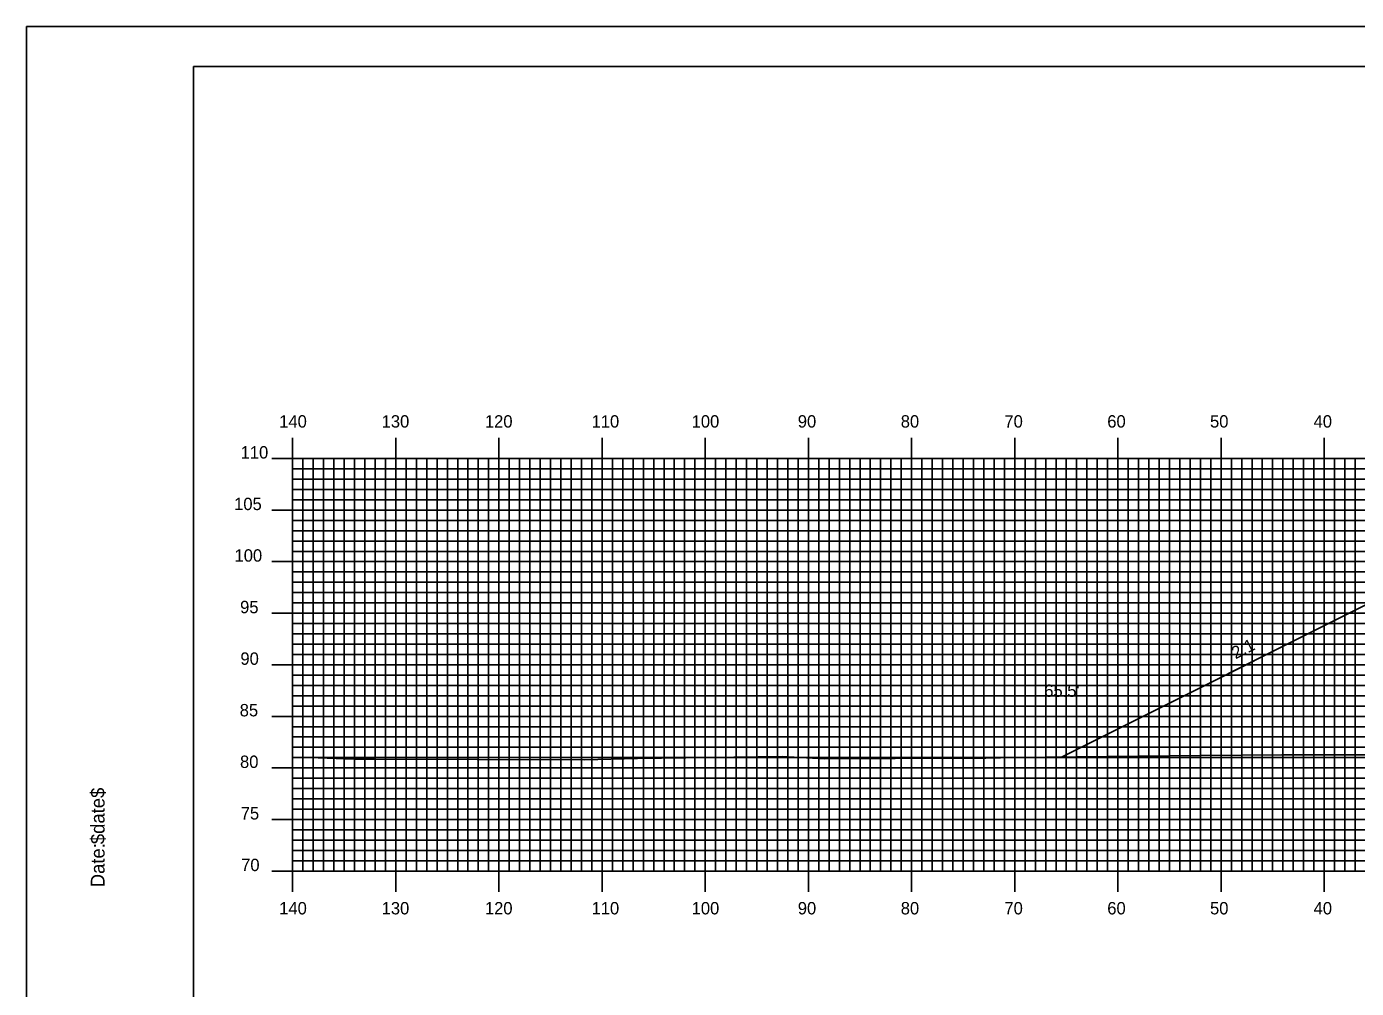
# Model space of a CAD drawing. Extents: x 1758643 to 1758986, y 442591 to 442811.
# Drawn here: x 1758642.9 to 1758771.8, y 442717.3 to 442810.5 of the extents above; entities that cross this region are included whole.
import ezdxf

# ---------------------------------------------------------------- set-up
doc = ezdxf.new("R2010")
doc.units = 0
for name, color, linetype in [('ANNOTATION', 7, 'Continuous'), ('BORDER', 7, 'Continuous'), ('D_Roadway_Centerline', 7, 'Continuous'), ('D_Roadway_SlopeLines', 7, 'Continuous'), ('D_Text_Standard', 7, 'Continuous'), ('H_V ANNOTATION', 7, 'Continuous'), ('MAJOR', 7, 'Continuous'), ('MINOR', 7, 'Continuous'), ('PLOT BOUNDARY', 7, 'Continuous'), ('S_Roadway_Centerline', 7, 'Continuous')]:
    doc.layers.add(name, color=color, linetype=linetype)

msp = doc.modelspace()

# ---------------------------------------------------------------- linework, layer by layer
at = {"layer": 'BORDER'}
msp.add_lwpolyline([(1758659.05, 442596.67), (1758979.05, 442596.67), (1758979.05, 442806.67), (1758659.05, 442806.67)], close=True, dxfattribs=at)
at = {"layer": 'D_Roadway_Centerline'}
msp.add_lwpolyline([(1758743.18, 442739.72), (1758775.52, 442755.9), (1758780.64, 442758.45), (1758783.64, 442758.57), (1758791.64, 442758.89), (1758796.65, 442759.05), (1758808.65, 442759.42), (1758820.65, 442759.78), (1758832.65, 442759.68), (1758840.65, 442759.36), (1758843.65, 442759.24), (1758848.4, 442756.87), (1758881.86, 442740.14)], dxfattribs=at)
at = {"layer": 'D_Roadway_SlopeLines'}
msp.add_lwpolyline([(1758780.64, 442758.45), (1758743.18, 442739.72)], dxfattribs=at)
at = {"layer": 'MAJOR'}
for p, q in [((1758668.65, 442770.67), (1758668.65, 442768.67)), ((1758678.65, 442770.67), (1758678.65, 442768.67)), ((1758688.65, 442770.67), (1758688.65, 442768.67)), ((1758698.65, 442770.67), (1758698.65, 442768.67)), ((1758708.65, 442770.67), (1758708.65, 442768.67)), ((1758718.65, 442770.67), (1758718.65, 442768.67)), ((1758728.65, 442770.67), (1758728.65, 442768.67)), ((1758738.65, 442770.67), (1758738.65, 442768.67)), ((1758748.65, 442770.67), (1758748.65, 442768.67)), ((1758758.65, 442770.67), (1758758.65, 442768.67)), ((1758768.65, 442770.67), (1758768.65, 442768.67)), ((1758666.64, 442768.67), (1758668.65, 442768.67)), ((1758668.65, 442768.67), (1758948.65, 442768.67)), ((1758668.65, 442728.67), (1758668.65, 442768.67)), ((1758668.65, 442728.67), (1758668.65, 442768.67)), ((1758668.65, 442768.67), (1758948.65, 442768.67)), ((1758678.65, 442728.67), (1758678.65, 442768.67)), ((1758688.65, 442728.67), (1758688.65, 442768.67)), ((1758698.65, 442728.67), (1758698.65, 442768.67)), ((1758708.65, 442728.67), (1758708.65, 442768.67)), ((1758718.65, 442728.67), (1758718.65, 442768.67)), ((1758728.65, 442728.67), (1758728.65, 442768.67)), ((1758738.65, 442728.67), (1758738.65, 442768.67)), ((1758748.65, 442728.67), (1758748.65, 442768.67)), ((1758758.65, 442728.67), (1758758.65, 442768.67)), ((1758768.65, 442728.67), (1758768.65, 442768.67)), ((1758666.64, 442763.67), (1758668.65, 442763.67)), ((1758668.65, 442763.67), (1758948.65, 442763.67)), ((1758666.64, 442758.67), (1758668.65, 442758.67)), ((1758668.65, 442758.67), (1758948.65, 442758.67)), ((1758666.64, 442753.67), (1758668.65, 442753.67)), ((1758668.65, 442753.67), (1758948.65, 442753.67)), ((1758666.64, 442748.67), (1758668.65, 442748.67)), ((1758668.65, 442748.67), (1758948.65, 442748.67)), ((1758666.64, 442743.67), (1758668.65, 442743.67)), ((1758668.65, 442743.67), (1758948.65, 442743.67)), ((1758666.64, 442738.67), (1758668.65, 442738.67)), ((1758668.65, 442738.67), (1758948.65, 442738.67)), ((1758666.64, 442733.67), (1758668.65, 442733.67)), ((1758668.65, 442733.67), (1758948.65, 442733.67)), ((1758666.64, 442728.67), (1758668.65, 442728.67)), ((1758668.65, 442728.67), (1758948.65, 442728.67)), ((1758668.65, 442728.67), (1758948.65, 442728.67)), ((1758668.65, 442726.66), (1758668.65, 442728.67)), ((1758678.65, 442726.66), (1758678.65, 442728.67)), ((1758688.65, 442726.66), (1758688.65, 442728.67)), ((1758698.65, 442726.66), (1758698.65, 442728.67)), ((1758708.65, 442726.66), (1758708.65, 442728.67)), ((1758718.65, 442726.66), (1758718.65, 442728.67)), ((1758728.65, 442726.66), (1758728.65, 442728.67)), ((1758738.65, 442726.66), (1758738.65, 442728.67)), ((1758748.65, 442726.66), (1758748.65, 442728.67)), ((1758758.65, 442726.66), (1758758.65, 442728.67)), ((1758768.65, 442726.66), (1758768.65, 442728.67))]:
    msp.add_line(p, q, dxfattribs=at)
at = {"layer": 'MINOR'}
for p, q in [((1758668.65, 442767.67), (1758948.65, 442767.67)), ((1758668.65, 442767.67), (1758670.65, 442767.67)), ((1758669.65, 442728.67), (1758669.65, 442768.67)), ((1758670.65, 442728.67), (1758670.65, 442768.67)), ((1758671.65, 442728.67), (1758671.65, 442768.67)), ((1758672.65, 442728.67), (1758672.65, 442768.67)), ((1758673.65, 442728.67), (1758673.65, 442768.67)), ((1758674.65, 442728.67), (1758674.65, 442768.67)), ((1758675.65, 442728.67), (1758675.65, 442768.67)), ((1758676.65, 442728.67), (1758676.65, 442768.67)), ((1758677.65, 442728.67), (1758677.65, 442768.67)), ((1758679.65, 442728.67), (1758679.65, 442768.67)), ((1758680.65, 442728.67), (1758680.65, 442768.67)), ((1758681.65, 442728.67), (1758681.65, 442768.67)), ((1758682.65, 442728.67), (1758682.65, 442768.67)), ((1758683.65, 442728.67), (1758683.65, 442768.67)), ((1758684.65, 442728.67), (1758684.65, 442768.67)), ((1758685.65, 442728.67), (1758685.65, 442768.67)), ((1758686.65, 442728.67), (1758686.65, 442768.67)), ((1758687.65, 442728.67), (1758687.65, 442768.67)), ((1758689.65, 442728.67), (1758689.65, 442768.67)), ((1758690.65, 442728.67), (1758690.65, 442768.67)), ((1758691.65, 442728.67), (1758691.65, 442768.67)), ((1758692.65, 442728.67), (1758692.65, 442768.67)), ((1758693.65, 442728.67), (1758693.65, 442768.67)), ((1758694.65, 442728.67), (1758694.65, 442768.67)), ((1758695.65, 442728.67), (1758695.65, 442768.67)), ((1758696.65, 442728.67), (1758696.65, 442768.67)), ((1758697.65, 442728.67), (1758697.65, 442768.67)), ((1758699.65, 442728.67), (1758699.65, 442768.67)), ((1758700.65, 442728.67), (1758700.65, 442768.67)), ((1758701.65, 442728.67), (1758701.65, 442768.67)), ((1758702.65, 442728.67), (1758702.65, 442768.67)), ((1758703.65, 442728.67), (1758703.65, 442768.67)), ((1758704.65, 442728.67), (1758704.65, 442768.67)), ((1758705.65, 442728.67), (1758705.65, 442768.67)), ((1758706.65, 442728.67), (1758706.65, 442768.67)), ((1758707.65, 442728.67), (1758707.65, 442768.67)), ((1758709.65, 442728.67), (1758709.65, 442768.67)), ((1758710.65, 442728.67), (1758710.65, 442768.67)), ((1758711.65, 442728.67), (1758711.65, 442768.67)), ((1758712.65, 442728.67), (1758712.65, 442768.67)), ((1758713.65, 442728.67), (1758713.65, 442768.67)), ((1758714.65, 442728.67), (1758714.65, 442768.67)), ((1758715.65, 442728.67), (1758715.65, 442768.67)), ((1758716.65, 442728.67), (1758716.65, 442768.67)), ((1758717.65, 442728.67), (1758717.65, 442768.67)), ((1758719.65, 442728.67), (1758719.65, 442768.67)), ((1758720.65, 442728.67), (1758720.65, 442768.67)), ((1758721.65, 442728.67), (1758721.65, 442768.67)), ((1758722.65, 442728.67), (1758722.65, 442768.67)), ((1758723.65, 442728.67), (1758723.65, 442768.67)), ((1758724.65, 442728.67), (1758724.65, 442768.67)), ((1758725.65, 442728.67), (1758725.65, 442768.67)), ((1758726.65, 442728.67), (1758726.65, 442768.67)), ((1758727.65, 442728.67), (1758727.65, 442768.67)), ((1758729.65, 442728.67), (1758729.65, 442768.67)), ((1758730.65, 442728.67), (1758730.65, 442768.67)), ((1758731.65, 442728.67), (1758731.65, 442768.67)), ((1758732.65, 442728.67), (1758732.65, 442768.67)), ((1758733.65, 442728.67), (1758733.65, 442768.67)), ((1758734.65, 442728.67), (1758734.65, 442768.67)), ((1758735.65, 442728.67), (1758735.65, 442768.67)), ((1758736.65, 442728.67), (1758736.65, 442768.67)), ((1758737.65, 442728.67), (1758737.65, 442768.67)), ((1758739.65, 442728.67), (1758739.65, 442768.67)), ((1758740.65, 442728.67), (1758740.65, 442768.67)), ((1758741.65, 442728.67), (1758741.65, 442768.67)), ((1758742.65, 442728.67), (1758742.65, 442768.67)), ((1758743.65, 442728.67), (1758743.65, 442768.67)), ((1758744.65, 442728.67), (1758744.65, 442768.67)), ((1758745.65, 442728.67), (1758745.65, 442768.67)), ((1758746.65, 442728.67), (1758746.65, 442768.67)), ((1758747.65, 442728.67), (1758747.65, 442768.67)), ((1758749.65, 442728.67), (1758749.65, 442768.67)), ((1758750.65, 442728.67), (1758750.65, 442768.67)), ((1758751.65, 442728.67), (1758751.65, 442768.67)), ((1758752.65, 442728.67), (1758752.65, 442768.67)), ((1758753.65, 442728.67), (1758753.65, 442768.67)), ((1758754.65, 442728.67), (1758754.65, 442768.67)), ((1758755.65, 442728.67), (1758755.65, 442768.67)), ((1758756.65, 442728.67), (1758756.65, 442768.67)), ((1758757.65, 442728.67), (1758757.65, 442768.67)), ((1758759.65, 442728.67), (1758759.65, 442768.67)), ((1758760.65, 442728.67), (1758760.65, 442768.67)), ((1758761.65, 442728.67), (1758761.65, 442768.67)), ((1758762.65, 442728.67), (1758762.65, 442768.67)), ((1758763.65, 442728.67), (1758763.65, 442768.67)), ((1758764.65, 442728.67), (1758764.65, 442768.67)), ((1758765.65, 442728.67), (1758765.65, 442768.67)), ((1758766.65, 442728.67), (1758766.65, 442768.67)), ((1758767.65, 442728.67), (1758767.65, 442768.67)), ((1758769.65, 442728.67), (1758769.65, 442768.67)), ((1758770.65, 442728.67), (1758770.65, 442768.67)), ((1758771.65, 442728.67), (1758771.65, 442768.67)), ((1758668.65, 442766.67), (1758948.65, 442766.67)), ((1758668.65, 442766.67), (1758670.65, 442766.67)), ((1758668.65, 442765.67), (1758948.65, 442765.67)), ((1758668.65, 442765.67), (1758670.65, 442765.67)), ((1758668.65, 442764.67), (1758948.65, 442764.67)), ((1758668.65, 442764.67), (1758670.65, 442764.67)), ((1758668.65, 442762.67), (1758948.65, 442762.67)), ((1758668.65, 442762.67), (1758670.65, 442762.67)), ((1758668.65, 442761.67), (1758948.65, 442761.67)), ((1758668.65, 442761.67), (1758670.65, 442761.67)), ((1758668.65, 442760.67), (1758948.65, 442760.67)), ((1758668.65, 442760.67), (1758670.65, 442760.67)), ((1758668.65, 442759.67), (1758948.65, 442759.67)), ((1758668.65, 442759.67), (1758670.65, 442759.67)), ((1758668.65, 442757.67), (1758948.65, 442757.67)), ((1758668.65, 442757.67), (1758670.65, 442757.67)), ((1758668.65, 442756.67), (1758948.65, 442756.67)), ((1758668.65, 442756.67), (1758670.65, 442756.67)), ((1758668.65, 442755.67), (1758948.65, 442755.67)), ((1758668.65, 442755.67), (1758670.65, 442755.67)), ((1758668.65, 442754.67), (1758948.65, 442754.67)), ((1758668.65, 442754.67), (1758670.65, 442754.67)), ((1758668.65, 442752.67), (1758948.65, 442752.67)), ((1758668.65, 442752.67), (1758670.65, 442752.67)), ((1758668.65, 442751.67), (1758948.65, 442751.67)), ((1758668.65, 442751.67), (1758670.65, 442751.67)), ((1758668.65, 442750.67), (1758948.65, 442750.67)), ((1758668.65, 442750.67), (1758670.65, 442750.67)), ((1758668.65, 442749.67), (1758948.65, 442749.67)), ((1758668.65, 442749.67), (1758670.65, 442749.67)), ((1758668.65, 442747.67), (1758948.65, 442747.67)), ((1758668.65, 442747.67), (1758670.65, 442747.67)), ((1758668.65, 442746.67), (1758948.65, 442746.67)), ((1758668.65, 442746.67), (1758670.65, 442746.67)), ((1758668.65, 442745.67), (1758948.65, 442745.67)), ((1758668.65, 442745.67), (1758670.65, 442745.67)), ((1758668.65, 442744.67), (1758948.65, 442744.67)), ((1758668.65, 442744.67), (1758670.65, 442744.67)), ((1758668.65, 442742.67), (1758948.65, 442742.67)), ((1758668.65, 442742.67), (1758670.65, 442742.67)), ((1758668.65, 442741.67), (1758948.65, 442741.67)), ((1758668.65, 442741.67), (1758670.65, 442741.67)), ((1758668.65, 442740.67), (1758948.65, 442740.67)), ((1758668.65, 442740.67), (1758670.65, 442740.67)), ((1758668.65, 442739.67), (1758948.65, 442739.67)), ((1758668.65, 442739.67), (1758670.65, 442739.67)), ((1758668.65, 442737.67), (1758948.65, 442737.67)), ((1758668.65, 442737.67), (1758670.65, 442737.67)), ((1758668.65, 442736.67), (1758948.65, 442736.67)), ((1758668.65, 442736.67), (1758670.65, 442736.67)), ((1758668.65, 442735.67), (1758948.65, 442735.67)), ((1758668.65, 442735.67), (1758670.65, 442735.67)), ((1758668.65, 442734.67), (1758948.65, 442734.67)), ((1758668.65, 442734.67), (1758670.65, 442734.67)), ((1758668.65, 442732.67), (1758948.65, 442732.67)), ((1758668.65, 442732.67), (1758670.65, 442732.67)), ((1758668.65, 442731.67), (1758948.65, 442731.67)), ((1758668.65, 442731.67), (1758670.65, 442731.67)), ((1758668.65, 442730.67), (1758948.65, 442730.67)), ((1758668.65, 442730.67), (1758670.65, 442730.67)), ((1758668.65, 442729.67), (1758948.65, 442729.67)), ((1758668.65, 442729.67), (1758670.65, 442729.67))]:
    msp.add_line(p, q, dxfattribs=at)
at = {"layer": 'PLOT BOUNDARY'}
msp.add_lwpolyline([(1758642.86, 442590.55), (1758982.86, 442590.55), (1758982.86, 442810.55), (1758642.86, 442810.55)], close=True, dxfattribs=at)
at = {"layer": 'S_Roadway_Centerline'}
msp.add_lwpolyline([(1758668.65, 442739.69), (1758671.12, 442739.66), (1758674.63, 442739.52), (1758676.66, 442739.53), (1758686.53, 442739.49), (1758696.93, 442739.46), (1758702.09, 442739.6), (1758716.11, 442739.79), (1758720.2, 442739.54), (1758733.91, 442739.62), (1758735.2, 442739.62), (1758735.84, 442739.62), (1758738.72, 442739.67), (1758756.65, 442739.89), (1758764.54, 442739.94), (1758774.35, 442739.95)], dxfattribs=at)

# ---------------------------------------------------------------- texts
at = {"layer": 'ANNOTATION'}
msp.add_text('2:1', height=1.2, rotation=26.5651, dxfattribs=at).set_placement((1758760.05, 442749.2))
at = {"layer": 'BORDER'}
for s, p in [('$date$', (1758650.42, 442731.28)), ('$date$', (1758650.42, 442731.28)), ('Date:', (1758650.42, 442727.1)), ('Date:', (1758650.42, 442727.1))]:
    msp.add_text(s, height=1.339, rotation=90, dxfattribs=at).set_placement(p)
at = {"layer": 'D_Text_Standard'}
msp.add_text("65.5'", height=1.2, dxfattribs=at).set_placement((1758741.51, 442745.56))
at = {"layer": 'H_V ANNOTATION'}
for s, p in [('140', (1758667.35, 442771.67)), ('130', (1758677.28, 442771.67)), ('120', (1758687.29, 442771.67)), ('110', (1758697.63, 442771.67)), ('100', (1758707.33, 442771.67)), ('90', (1758717.62, 442771.67)), ('80', (1758727.6, 442771.67)), ('70', (1758737.65, 442771.67)), ('60', (1758747.62, 442771.67)), ('50', (1758757.58, 442771.67)), ('40', (1758767.62, 442771.67)), ('110', (1758663.61, 442768.67)), ('105', (1758662.98, 442763.67)), ('100', (1758663.02, 442758.67)), ('95', (1758663.56, 442753.67)), ('90', (1758663.59, 442748.67)), ('85', (1758663.52, 442743.67)), ('80', (1758663.55, 442738.67)), ('75', (1758663.62, 442733.67)), ('70', (1758663.66, 442728.67)), ('140', (1758667.35, 442724.47)), ('130', (1758677.28, 442724.47)), ('120', (1758687.29, 442724.47)), ('110', (1758697.63, 442724.47)), ('100', (1758707.33, 442724.47)), ('90', (1758717.62, 442724.47)), ('80', (1758727.6, 442724.47)), ('70', (1758737.65, 442724.47)), ('60', (1758747.62, 442724.47)), ('50', (1758757.58, 442724.47)), ('40', (1758767.62, 442724.47))]:
    msp.add_text(s, height=1.2, dxfattribs=at).set_placement(p)
at = {"layer": 'MAJOR'}
msp.add_text('-', height=0.012, dxfattribs=at).set_placement((1758668.64, 442728.67))

doc.saveas('drawing.dxf')
